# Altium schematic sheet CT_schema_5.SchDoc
size 357 x 214 mm
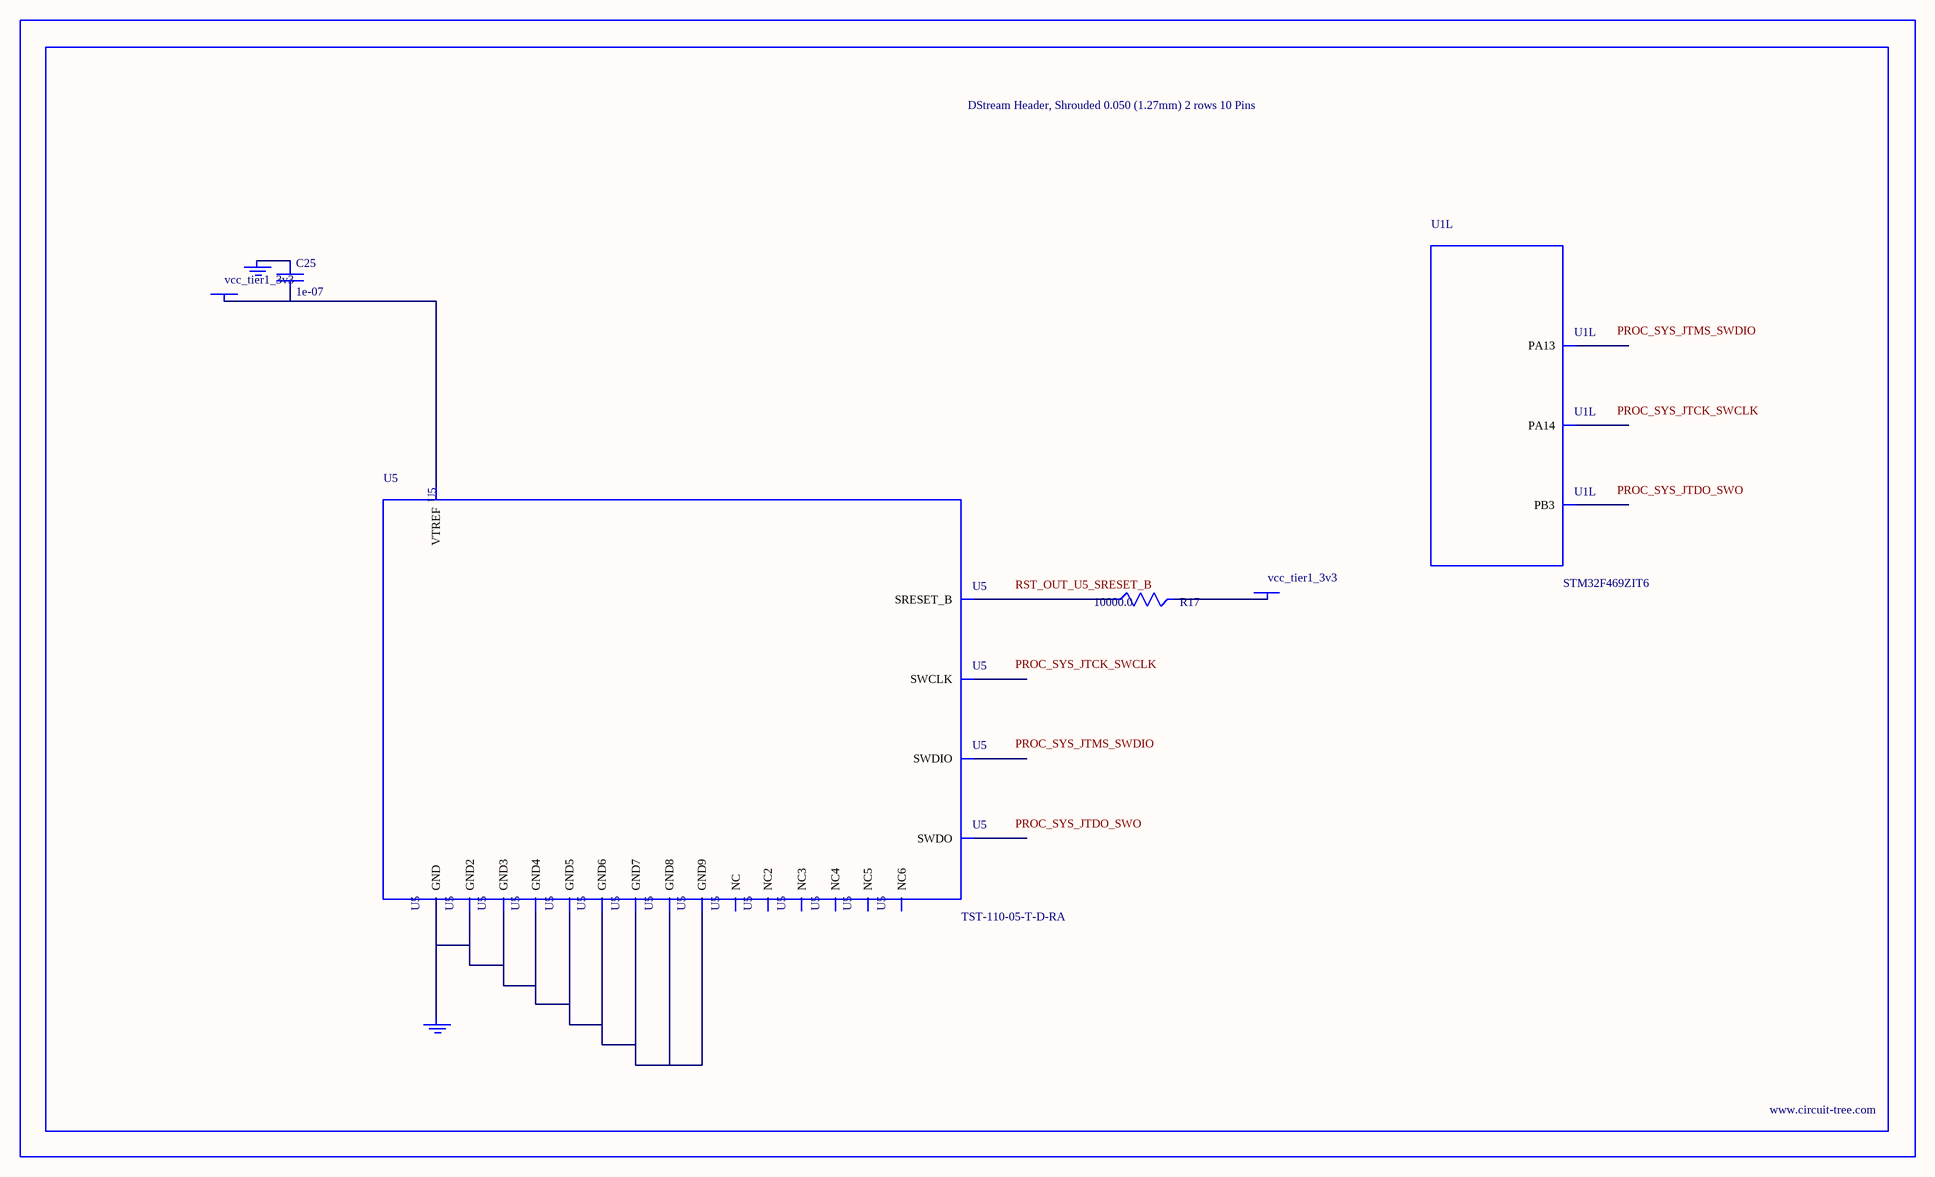
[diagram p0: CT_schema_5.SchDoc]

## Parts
BORDER4  (no value)
C25  1e-07  [C0402]
GND_INSTANCE_4_0  (no value)
GND_INSTANCE_4_1  (no value)
POWER_INSTANCE_4_0  vcc_tier1_3v3
POWER_INSTANCE_4_1  vcc_tier1_3v3
R17  10000.0  [R0603]
U1  STM32F469ZIT6  [LQFP144]  (part L of 14)
U5  TST-110-05-T-D-RA  [TST-110-05-T-D-RA]

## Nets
NetC25_1: C25.1 GND_INSTANCE_4_0.0(GND)
NetC25_2: C25.2 POWER_INSTANCE_4_0.0(PWR) U5.1(VTREF)
NetGND_INSTANCE_4_1_0: GND_INSTANCE_4_1.0(GND) U5.4(GND) U5.6(GND2) U5.8(GND3) U5.10(GND4) U5.12(GND5) U5.14(GND6) U5.16(GND7) U5.18(GND8) U5.20(GND9)
NetPOWER_INSTANCE_4_1_0: POWER_INSTANCE_4_1.0(PWR) R17.2
NetR17_1: R17.1 U5.15(SRESET_B)

Not connected (* = marked no-connect by the designer): U1 107(PA13) 111(PA14) 132(PB3); U5 2(NC) 3(NC2) 5(NC3) 7(SWDIO) 9(SWCLK) 11(NC4) 13(SWDO) 17(NC5) 19(NC6)

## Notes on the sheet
- Labels drawn without touching a wire or pin: PROC_SYS_JTCK_SWCLK, PROC_SYS_JTDO_SWO, PROC_SYS_JTMS_SWDIO, RST_OUT_U5_SRESET_B

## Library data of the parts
BORDER4 = BORDER_PAGE4
C25 = C0402C104K3RACTU
GND_INSTANCE_4_0 GND_INSTANCE_4_1 = GND
POWER_INSTANCE_4_0 POWER_INSTANCE_4_1 = PWR
R17 = RC0603JR-0710KL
